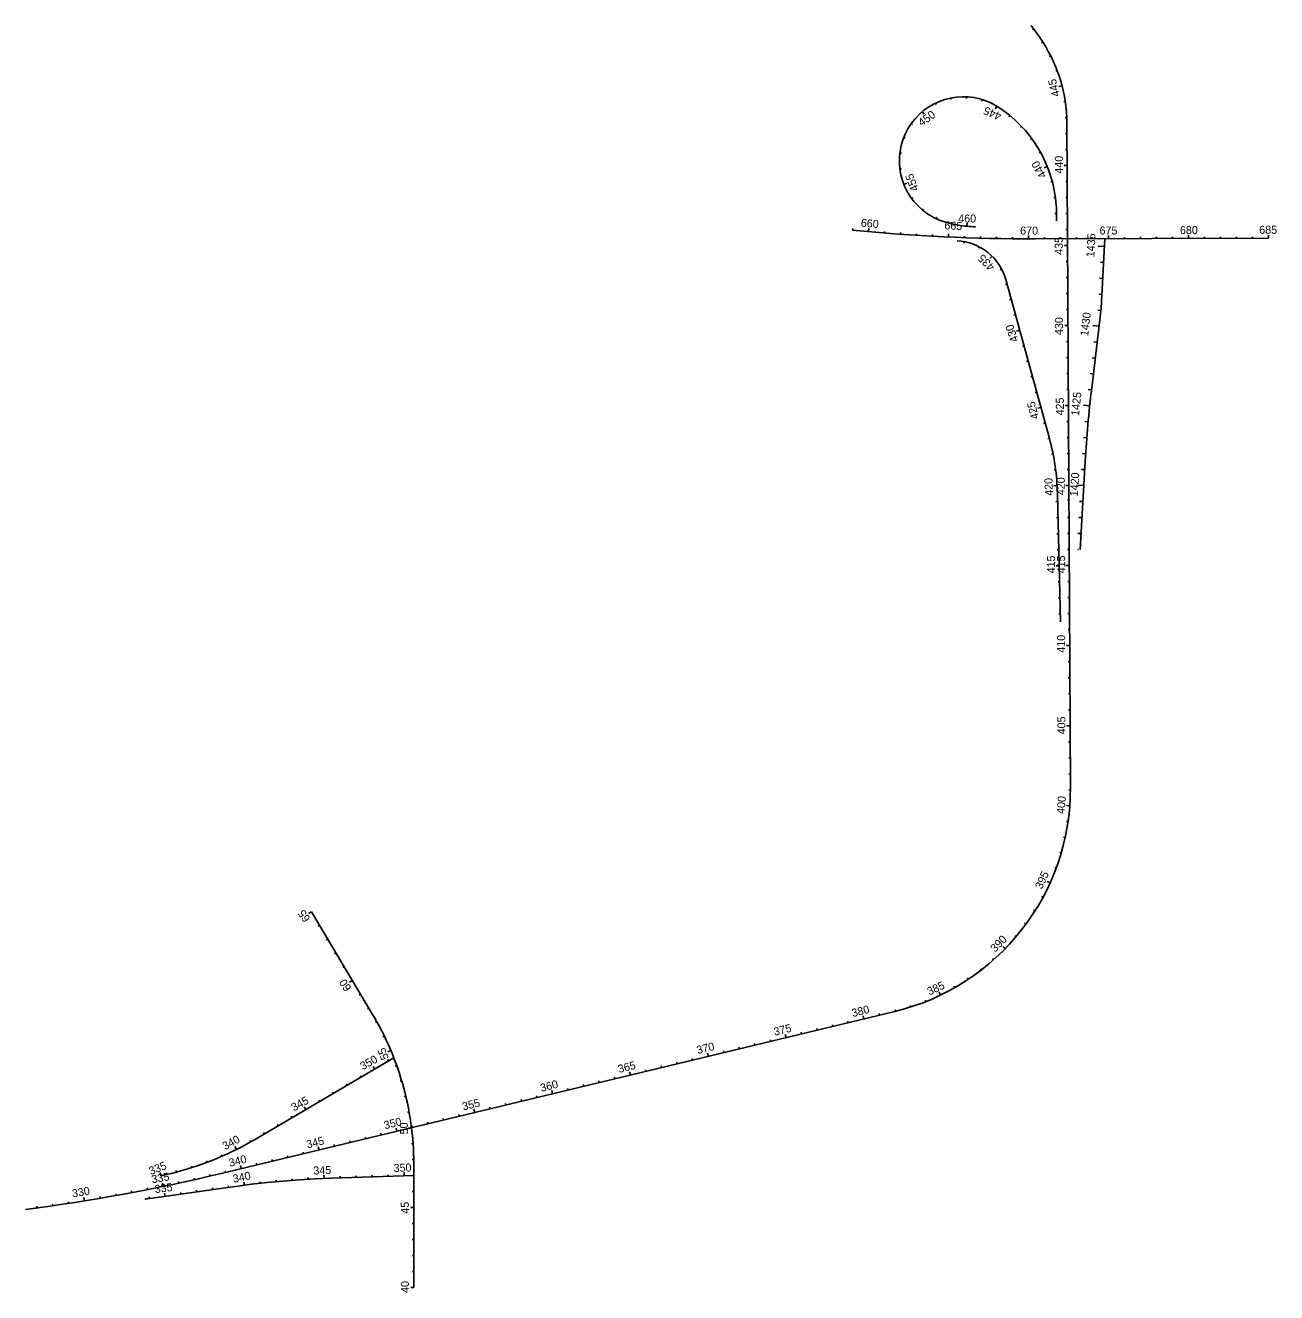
# Model space of a CAD drawing. Extents: x 448091 to 665917, y 1461380 to 1587607.
# Drawn here: x 588301 to 596117, y 1531698 to 1539615 of the extents above; entities that cross this region are included whole.
import ezdxf

# ---------------------------------------------------------------- set-up
doc = ezdxf.new("R2010")
doc.units = 0
doc.layers.add('TextShtNo', color=7, linetype='Continuous')
doc.layers.add('TextTitle', color=7, linetype='Continuous')

msp = doc.modelspace()

# ---------------------------------------------------------------- linework, layer by layer
at = {"layer": 'TextShtNo'}
for p, q in [((594807.2, 1539001), (594810.8, 1538304.1)), ((594742.4, 1538392.9), (594742.1, 1538437.7)), ((594608.9, 1538280.9), (596066.2, 1538284.4)), ((594810.8, 1538304.1), (594828.8, 1534854.9)), ((595020.8, 1537847.2), (595044.1, 1538282.5)), ((594697.4, 1537034.2), (594424.4, 1538026.1)), ((594961.4, 1537347.6), (595020.8, 1537847.2)), ((594888.8, 1536340.3), (594921, 1536890.8)), ((594767.4, 1535889.4), (594747.3, 1536687.2)), ((590469.4, 1533436.6), (590087.5, 1534077.8)), ((590481, 1533416.9), (590469.4, 1533436.6)), ((590496.8, 1533389.1), (590481, 1533416.9)), ((590512.2, 1533361.1), (590496.8, 1533389.1)), ((590526.9, 1533332.7), (590512.2, 1533361.1)), ((590541.2, 1533304.1), (590526.9, 1533332.7)), ((590555, 1533275.2), (590541.2, 1533304.1)), ((590568.4, 1533246.1), (590555, 1533275.2)), ((590581, 1533216.8), (590568.4, 1533246.1)), ((590593.3, 1533187.3), (590581, 1533216.8)), ((589727.7, 1532651.4), (590602.6, 1533164)), ((590605.1, 1533157.6), (590593.3, 1533187.3)), ((590616.3, 1533127.6), (590605.1, 1533157.6)), ((590627, 1533097.6), (590616.3, 1533127.6)), ((590637.3, 1533067.2), (590627, 1533097.6)), ((590646.8, 1533036.8), (590637.3, 1533067.2)), ((590656, 1533006), (590646.8, 1533036.8)), ((590664.5, 1532975.2), (590656, 1533006)), ((590672.6, 1532944.3), (590664.5, 1532975.2)), ((590680.1, 1532913.3), (590672.6, 1532944.3)), ((590687.1, 1532882), (590680.1, 1532913.3)), ((590693.4, 1532850.7), (590687.1, 1532882)), ((590699.3, 1532819.4), (590693.4, 1532850.7)), ((590704.6, 1532787.7), (590699.3, 1532819.4)), ((590709.4, 1532756.2), (590704.6, 1532787.7)), ((590713.7, 1532724.5), (590709.4, 1532756.2)), ((590717.2, 1532692.6), (590713.7, 1532724.5)), ((589707.3, 1532639.5), (589727.7, 1532651.4)), ((590720.3, 1532660.9), (590717.2, 1532692.6)), ((590722.9, 1532629), (590720.3, 1532660.9)), ((589559.1, 1532563.5), (589589.2, 1532577.7)), ((589589.2, 1532577.7), (589619.1, 1532592.5)), ((589619.1, 1532592.5), (589648.7, 1532607.5)), ((589648.7, 1532607.5), (589678.2, 1532623.4)), ((589678.2, 1532623.4), (589707.3, 1532639.5)), ((590724.8, 1532597), (590722.9, 1532629)), ((590726.3, 1532565.1), (590724.8, 1532597)), ((590727.3, 1532533.2), (590726.3, 1532565.1)), ((589341.5, 1532479.4), (589373.3, 1532489.7)), ((589373.3, 1532489.7), (589404.8, 1532500.7)), ((589404.8, 1532500.7), (589435.9, 1532512.2)), ((589435.9, 1532512.2), (589467.2, 1532524.3)), ((589467.2, 1532524.3), (589497.9, 1532536.9)), ((589497.9, 1532536.9), (589528.6, 1532549.8)), ((589528.6, 1532549.8), (589559.1, 1532563.5)), ((590727.5, 1532501.2), (590727.3, 1532533.2)), ((590728.3, 1531729.5), (590727.5, 1532501.2)), ((589148.1, 1532428.8), (589180.8, 1532435.8)), ((589180.8, 1532435.8), (589213.2, 1532443.4)), ((589213.2, 1532443.4), (589245.4, 1532451.6)), ((589245.4, 1532451.6), (589277.8, 1532460.3)), ((589277.8, 1532460.3), (589309.8, 1532469.6)), ((589309.8, 1532469.6), (589341.5, 1532479.4)), ((590011.7, 1532403), (590111.2, 1532409.1)), ((590111.2, 1532409.1), (590211.4, 1532412.9)), ((590211.4, 1532412.9), (590727.6, 1532429.5)), ((590211.4, 1532412.9), (590211.4, 1532412.9)), ((589050, 1532282.7), (589595.4, 1532359.6)), ((589595.4, 1532359.6), (589614, 1532362.1)), ((589595.4, 1532359.6), (589595.4, 1532359.6)), ((589614, 1532362.1), (589712.7, 1532375)), ((589712.7, 1532375), (589812.1, 1532386.2)), ((589812.1, 1532386.2), (589912.2, 1532395.2)), ((589912.2, 1532395.2), (590011.7, 1532403))]:
    msp.add_line(p, q, dxfattribs=at)
for points in [[(594632.8, 1539544.7), (594583.4, 1539614.6)], [(593905.5, 1538460.3), (593908.3, 1538458), (593913.7, 1538453.7), (593919.3, 1538449.4), (593924.9, 1538445.3), (593930.6, 1538441.2), (593936.3, 1538437.2), (593942.2, 1538433.4), (593948, 1538429.6), (593954, 1538426), (593960, 1538422.4), (593966.1, 1538419), (593972.2, 1538415.6), (593978.4, 1538412.4), (593984.6, 1538409.3), (593991, 1538406.3), (593997.3, 1538403.4), (594003.7, 1538400.6), (594010.2, 1538397.9), (594016.6, 1538395.4), (594023.2, 1538392.9), (594029.8, 1538390.6), (594036.4, 1538388.4), (594043, 1538386.3), (594049.7, 1538384.3), (594056.4, 1538382.4), (594058.1, 1538382), (594058.1, 1538382), (594071.6, 1538378.5), (594085.2, 1538375.3), (594098.8, 1538372.4), (594112.6, 1538369.6), (594126.3, 1538367.1), (594140, 1538364.9), (594153.9, 1538362.8), (594167.7, 1538361), (594181.6, 1538359.5), (594182.4, 1538359.5)], [(594742.1, 1538437.7), (594742, 1538451.5), (594741.5, 1538465.5), (594740.8, 1538479.4), (594740.2, 1538488.9)], [(594182.4, 1538359.5), (594195.5, 1538358.3), (594209.4, 1538357.2), (594223.3, 1538356.4), (594235.8, 1538355.9)], [(589524.8, 1532443.3), (593731.3, 1533454.8)]]:
    msp.add_lwpolyline(points, dxfattribs=at)
for centre, radius, start, end in [((593857.2, 1538996.1), 950, 0.29776, 35.26971), ((594160.2, 1538768.7), 400, 58.54689, 230.43574), ((593942.1, 1538433.3), 800, 3.98524, 57.75864), ((594581.1, 1549718), 11437.2, 264.41492, 270.13917), ((594106.2, 1537938.5), 330, 15.38847, 87.53834), ((602547.4, 1536445.8), 7639.4, 173.22068, 176.66075), ((593315.2, 1536658.3), 1432.4, 1.15557, 15.21148), ((593396.4, 1534847.5), 1432.4, 283.52028, 0.29778), ((586845.8, 1543584.9), 11459.2, 277.29529, 283.52026)]:
    msp.add_arc(centre, radius, start, end, dxfattribs=at)
at = {"layer": 'TextTitle'}
for p, q in [((594590.8, 1539586.7), (594599, 1539592.5)), ((594647.6, 1539504.9), (594656, 1539510.4)), ((594696.7, 1539419.1), (594705.6, 1539423.6)), ((594736.5, 1539328.5), (594745.8, 1539332.1)), ((594756.9, 1539231.8), (594776.2, 1539236.8)), ((594082.3, 1539150.9), (594080.3, 1539160.7)), ((594179.3, 1539158.3), (594179.8, 1539168.2)), ((594275.1, 1539141.4), (594278, 1539151)), ((594786.5, 1539137.5), (594796.4, 1539139)), ((593915.1, 1539059.1), (593902.2, 1539074.4)), ((593990.2, 1539119.7), (593985.9, 1539128.7)), ((594358.3, 1539093), (594368.9, 1539109.9)), ((593842.7, 1538995.2), (593834.6, 1539001)), ((594443.6, 1539043.7), (594450, 1539051.5)), ((594515.8, 1538976.4), (594523.1, 1538983.3)), ((594796.2, 1539039), (594806.2, 1539039.5)), ((593796.6, 1538909.7), (593787.3, 1538913.3)), ((594579.1, 1538900.7), (594587.1, 1538906.6)), ((594807.5, 1538939.6), (594797.5, 1538939.5)), ((594632.4, 1538817.6), (594641.1, 1538822.5)), ((594808.1, 1538839.6), (594798, 1538839.5)), ((593773, 1538815.3), (593763.1, 1538816.5)), ((594808.6, 1538739.6), (594788.6, 1538739.5)), ((593773.5, 1538718.1), (593763.6, 1538716.8)), ((594665.6, 1538724.8), (594684.2, 1538732.3)), ((593807.4, 1538627.7), (593788.8, 1538620.3)), ((594706, 1538634.9), (594715.7, 1538637.5)), ((594809.1, 1538639.6), (594799.1, 1538639.5)), ((593845.1, 1538538.9), (593837.1, 1538533)), ((594725.2, 1538538.1), (594735.1, 1538539.4)), ((594809.6, 1538539.6), (594799.6, 1538539.5)), ((593911.7, 1538467.9), (593905.4, 1538460.4)), ((593905.5, 1538460.3), (593905.4, 1538460.4)), ((594732.1, 1538439.6), (594742.1, 1538439.8)), ((594810.1, 1538439.6), (594800.1, 1538439.5)), ((593468, 1538335.1), (593469, 1538345.1)), ((593567.6, 1538325.8), (593569.4, 1538345.7)), ((593993.8, 1538415.5), (593989.6, 1538406.9)), ((594086.6, 1538385.1), (594084.4, 1538375.5)), ((594184.2, 1538379.4), (594182.4, 1538359.5)), ((593667.2, 1538317.4), (593668, 1538327.4)), ((593766.9, 1538309.8), (593767.7, 1538319.8)), ((593866.7, 1538303.2), (593867.3, 1538313.1)), ((593966.5, 1538297.3), (593967.1, 1538307.3)), ((594066.4, 1538292.4), (594067.3, 1538312.4)), ((594166.3, 1538288.3), (594166.7, 1538298.3)), ((594266.3, 1538285.2), (594266.6, 1538295.2)), ((594366.3, 1538282.8), (594366.4, 1538292.8)), ((594466.3, 1538281.4), (594466.4, 1538291.4)), ((594566.2, 1538280.8), (594566.3, 1538300.8)), ((594666.3, 1538281), (594666.2, 1538291)), ((594766.3, 1538281.2), (594766.2, 1538291.2)), ((594810.7, 1538339.6), (594800.6, 1538339.5)), ((594866.3, 1538281.5), (594866.2, 1538291.5)), ((594926.7, 1538288.1), (594923.8, 1538278.5)), ((594966.3, 1538281.7), (594966.2, 1538291.7)), ((595066.2, 1538282), (595066.2, 1538302)), ((595166.2, 1538282.2), (595166.2, 1538292.2)), ((595266.2, 1538282.5), (595266.2, 1538292.5)), ((595366.2, 1538282.7), (595366.2, 1538292.7)), ((595466.2, 1538282.9), (595466.2, 1538292.9)), ((595566.2, 1538283.2), (595566.2, 1538303.2)), ((595666.2, 1538283.4), (595666.2, 1538293.4)), ((595766.2, 1538283.7), (595766.2, 1538293.7)), ((595866.2, 1538283.9), (595866.2, 1538293.9)), ((595966.2, 1538284.2), (595966.2, 1538294.2)), ((596066.2, 1538284.4), (596066.2, 1538304.4)), ((594162.2, 1538253.6), (594164, 1538263.4)), ((594253.7, 1538222.5), (594258.3, 1538231.4)), ((594811.2, 1538239.6), (594791.2, 1538239.5)), ((595041.5, 1538233.1), (595001.5, 1538235.2)), ((594324.7, 1538158.5), (594338.8, 1538172.7)), ((594811.7, 1538139.6), (594801.7, 1538139.5)), ((595036.1, 1538133.2), (595016.1, 1538134.3)), ((594389.2, 1538088), (594398, 1538092.6)), ((594812.2, 1538039.7), (594802.2, 1538039.6)), ((595030.8, 1538033.4), (595010.8, 1538034.5)), ((594422.3, 1537996.2), (594431.9, 1537998.8)), ((594448.8, 1537899.8), (594458.5, 1537902.4)), ((594812.7, 1537939.7), (594802.7, 1537939.6)), ((595025.4, 1537933.5), (595005.4, 1537934.6)), ((594475.3, 1537803.4), (594485, 1537806)), ((594813.2, 1537839.7), (594803.2, 1537839.6)), ((595019.2, 1537833.8), (594999.3, 1537836.1)), ((594492.2, 1537704.3), (594511.5, 1537709.6)), ((594813.8, 1537739.7), (594793.8, 1537739.6)), ((594813.8, 1537739.7), (594803.5, 1537739.6)), ((595007.4, 1537734.5), (594967.7, 1537739.2)), ((594814.3, 1537639.7), (594804.3, 1537639.6)), ((594995.6, 1537635.2), (594975.7, 1537637.5)), ((594528.4, 1537610.5), (594538.1, 1537613.2)), ((594555, 1537514.1), (594564.6, 1537516.8)), ((594814.8, 1537539.7), (594804.8, 1537539.6)), ((594983.8, 1537535.9), (594963.9, 1537538.2)), ((594581.5, 1537417.7), (594591.1, 1537420.3)), ((594815.3, 1537439.7), (594805.3, 1537439.6)), ((594972, 1537436.6), (594952.1, 1537438.9)), ((594608, 1537321.3), (594617.7, 1537323.9)), ((594815.8, 1537339.7), (594805.8, 1537339.6)), ((594960.2, 1537337.2), (594940.3, 1537339.6)), ((594816.4, 1537239.7), (594796.4, 1537239.6)), ((594949.2, 1537237.9), (594909.4, 1537242)), ((594624.9, 1537222.2), (594644.2, 1537227.5)), ((594661.1, 1537128.4), (594670.7, 1537131.1)), ((594816.9, 1537139.7), (594806.9, 1537139.6)), ((594939.4, 1537138.3), (594919.5, 1537140.1)), ((594687.8, 1537031.5), (594697.4, 1537034.2)), ((594817.4, 1537039.7), (594807.4, 1537039.6)), ((594931, 1537038.7), (594911.1, 1537040.2)), ((594710.4, 1536935.4), (594720.2, 1536937.4)), ((594817.9, 1536939.7), (594807.9, 1536939.6)), ((594923.9, 1536938.9), (594904, 1536940.2)), ((594726.3, 1536837.4), (594736.2, 1536838.7)), ((594818.4, 1536839.7), (594808.4, 1536839.6)), ((594917.9, 1536839.1), (594898, 1536840.3)), ((594725.4, 1536738), (594745.3, 1536739.1)), ((594819, 1536739.7), (594799, 1536739.6)), ((594912.1, 1536739.3), (594872.2, 1536741.6)), ((594738.5, 1536638.9), (594748.5, 1536639.2)), ((594819.4, 1536651.7), (594809.4, 1536651.6)), ((594906.3, 1536639.5), (594886.3, 1536640.6)), ((594741, 1536539), (594751, 1536539.2)), ((594820, 1536539.7), (594810, 1536539.6)), ((594900.5, 1536539.6), (594880.5, 1536540.8)), ((594743.6, 1536439), (594753.6, 1536439.2)), ((594820.5, 1536439.7), (594810.5, 1536439.6)), ((594894.6, 1536439.8), (594874.7, 1536441)), ((594746.1, 1536339), (594756.1, 1536339.3)), ((594821, 1536339.7), (594811, 1536339.6)), ((594879.1, 1536339.9), (594874.9, 1536340.2)), ((594738.6, 1536238.8), (594758.6, 1536239.3)), ((594821.6, 1536239.7), (594801.6, 1536239.6)), ((594751.1, 1536139.1), (594761.1, 1536139.3)), ((594822.1, 1536139.7), (594812.1, 1536139.6)), ((594753.6, 1536039.1), (594763.6, 1536039.4)), ((594822.6, 1536039.7), (594812.6, 1536039.6)), ((594756.1, 1535939.1), (594766.1, 1535939.4)), ((594823.1, 1535939.7), (594813.1, 1535939.6)), ((594823.6, 1535839.7), (594813.6, 1535839.6)), ((594824.2, 1535739.7), (594804.2, 1535739.6)), ((594824.7, 1535639.7), (594814.7, 1535639.6)), ((594825.2, 1535539.7), (594815.2, 1535539.6)), ((594825.7, 1535439.7), (594815.7, 1535439.6)), ((594826.2, 1535339.7), (594816.2, 1535339.7)), ((594826.8, 1535239.7), (594806.8, 1535239.6)), ((594827.3, 1535139.7), (594817.3, 1535139.7)), ((594827.8, 1535039.7), (594817.8, 1535039.7)), ((594828.3, 1534939.7), (594818.3, 1534939.7)), ((594828.8, 1534839.7), (594818.8, 1534839.8)), ((594824.7, 1534739.8), (594804.8, 1534741.3)), ((594813.7, 1534640.4), (594803.8, 1534641.9)), ((594795.8, 1534542.1), (594786.1, 1534544.2)), ((594771.1, 1534445.2), (594761.5, 1534448)), ((594739.7, 1534350.3), (594730.3, 1534353.7)), ((594701.8, 1534257.8), (594683.5, 1534266)), ((594657.5, 1534168.2), (594648.7, 1534172.9)), ((590087.5, 1534077.8), (590070.4, 1534067.5)), ((594607, 1534081.8), (594598.5, 1534087.2)), ((590138.7, 1533991.9), (590130.1, 1533986.7)), ((594550.6, 1533999.3), (594542.6, 1534005.2)), ((594488.7, 1533920.8), (594481, 1533927.3)), ((590189.9, 1533905.9), (590181.3, 1533900.8)), ((594421.4, 1533846.9), (594407.1, 1533860.8)), ((590241.1, 1533820), (590232.5, 1533814.9)), ((594349.1, 1533777.8), (594342.4, 1533785.3)), ((590292.2, 1533734.1), (590283.6, 1533729)), ((594272.1, 1533714), (594266, 1533721.9)), ((590343.4, 1533648.2), (590326.2, 1533638)), ((594105.9, 1533603.1), (594100.9, 1533611.8)), ((594190.9, 1533655.6), (594185.4, 1533664)), ((590394.6, 1533562.3), (590386, 1533557.2)), ((593925.8, 1533516.5), (593922.1, 1533525.8)), ((594017.3, 1533556.6), (594008.7, 1533574.7)), ((590445.8, 1533476.4), (590437.2, 1533471.2)), ((593635.7, 1533431.8), (593633.4, 1533441.5)), ((593735.4, 1533455.8), (593733, 1533465.5)), ((593831.6, 1533482.8), (593828.6, 1533492.3)), ((590496.2, 1533390), (590487.5, 1533385.1)), ((593344.1, 1533361.6), (593341.7, 1533371.4)), ((593441.3, 1533385), (593438.9, 1533394.7)), ((593538.5, 1533408.4), (593533.8, 1533427.8)), ((593538.5, 1533408.4), (593536.2, 1533418.1)), ((590542.5, 1533301.4), (590533.4, 1533297.1)), ((592955.1, 1533268.1), (592952.8, 1533277.9)), ((593052.4, 1533291.5), (593047.7, 1533311)), ((593149.6, 1533314.9), (593147.3, 1533324.6)), ((593246.8, 1533338.2), (593244.5, 1533348)), ((590583.7, 1533210.3), (590565.4, 1533202.6)), ((592663.5, 1533198), (592661.1, 1533207.7)), ((592760.7, 1533221.3), (592758.3, 1533231.1)), ((592857.9, 1533244.7), (592855.6, 1533254.5)), ((590570.1, 1533145), (590565.1, 1533153.6)), ((592371.8, 1533127.9), (592369.4, 1533137.6)), ((592469, 1533151.2), (592466.7, 1533161)), ((592566.2, 1533174.6), (592561.5, 1533194.1)), ((590397.6, 1533043.9), (590392.5, 1533052.5)), ((590483.9, 1533094.5), (590473.8, 1533111.7)), ((590620, 1533117.2), (590610.6, 1533113.8)), ((591982.9, 1533034.3), (591980.5, 1533044.1)), ((592080.1, 1533057.7), (592075.4, 1533077.2)), ((592177.3, 1533081.1), (592175, 1533090.8)), ((592274.5, 1533104.5), (592272.2, 1533114.2)), ((590311.3, 1532993.3), (590306.3, 1533002)), ((590651.2, 1533022.1), (590641.6, 1533019.3)), ((591593.9, 1532940.8), (591589.3, 1532960.3)), ((591691.2, 1532964.2), (591688.8, 1532973.9)), ((591788.4, 1532987.6), (591786, 1532997.3)), ((591885.6, 1533011), (591883.3, 1533020.7)), ((590138.7, 1532892.2), (590133.7, 1532900.9)), ((590225, 1532942.8), (590220, 1532951.4)), ((590677.1, 1532925.6), (590667.4, 1532923.2)), ((591302.2, 1532870.7), (591299.9, 1532880.4)), ((591399.5, 1532894.1), (591397.1, 1532903.8)), ((591496.7, 1532917.4), (591494.4, 1532927.2)), ((590052.5, 1532841.7), (590042.4, 1532858.9)), ((590697.7, 1532827.7), (590688, 1532825.9)), ((591010.6, 1532800.5), (591008.2, 1532810.3)), ((591107.8, 1532823.9), (591103.1, 1532843.4)), ((591205, 1532847.3), (591202.7, 1532857)), ((589879.9, 1532740.6), (589874.8, 1532749.2)), ((589966.2, 1532791.1), (589961.1, 1532799.8)), ((590621.6, 1532707), (590617, 1532726.5)), ((590713.1, 1532728.9), (590693.4, 1532726.3)), ((590713.1, 1532728.9), (590705.1, 1532727.9)), ((590718.9, 1532730.4), (590716.5, 1532740.1)), ((590816.1, 1532753.8), (590813.8, 1532763.5)), ((590913.3, 1532777.2), (590911, 1532786.9)), ((589707.3, 1532639.5), (589702.3, 1532648.2)), ((589793.6, 1532690), (589788.6, 1532698.7)), ((590330, 1532636.9), (590327.6, 1532646.6)), ((590427.2, 1532660.3), (590424.8, 1532670)), ((590524.4, 1532683.6), (590522.1, 1532693.4)), ((589619.1, 1532592.5), (589610, 1532610.3)), ((590038.3, 1532566.7), (590035.9, 1532576.5)), ((590135.5, 1532590.1), (590130.8, 1532609.6)), ((590232.7, 1532613.5), (590230.4, 1532623.2)), ((590722.9, 1532629.4), (590712.9, 1532628.6)), ((589341.5, 1532479.5), (589338.5, 1532489)), ((589436, 1532512.2), (589432.4, 1532521.5)), ((589528.7, 1532549.8), (589524.5, 1532559)), ((589649.4, 1532473.2), (589644.7, 1532492.7)), ((589746.6, 1532496.6), (589744.2, 1532506.3)), ((589843.8, 1532520), (589841.5, 1532529.7)), ((589941, 1532543.4), (589938.7, 1532553.1)), ((590727.3, 1532529.5), (590717.3, 1532529.5)), ((589148.1, 1532428.8), (589144, 1532448.4)), ((589245.5, 1532451.6), (589242.9, 1532461.3)), ((589357.3, 1532404.8), (589355.1, 1532414.1)), ((589454.7, 1532427.1), (589452.6, 1532436.5)), ((589552.1, 1532449.8), (589549.8, 1532459.6)), ((589967.4, 1532399.5), (589966.7, 1532409.5)), ((590067.2, 1532406.4), (590066.6, 1532416.4)), ((590167.1, 1532411.2), (590166.3, 1532431.2)), ((590267, 1532414.7), (590266.7, 1532424.7)), ((590367, 1532417.9), (590366.6, 1532427.9)), ((590466.9, 1532421.1), (590466.6, 1532431.1)), ((590566.9, 1532424.3), (590566.5, 1532434.3)), ((590666.8, 1532427.6), (590666.2, 1532447.6)), ((590727.6, 1532429.5), (590717.6, 1532429.5)), ((588965.6, 1532324), (588963.8, 1532333.4)), ((589063.9, 1532342.3), (589062, 1532352.3)), ((589161.8, 1532362.3), (589157.7, 1532381.8)), ((589259.7, 1532382.9), (589257.6, 1532392.7)), ((589371.9, 1532328.1), (589370.5, 1532338)), ((589470.9, 1532342.1), (589469.5, 1532352)), ((589569.9, 1532356), (589568.5, 1532365.9)), ((589669, 1532369.3), (589666.4, 1532389.1)), ((589768.3, 1532381.3), (589767.2, 1532391.2)), ((589867.8, 1532391.2), (589866.9, 1532401.2)), ((590727.7, 1532329.5), (590717.7, 1532329.5)), ((588472.5, 1532241.5), (588471.1, 1532251.7)), ((588571.3, 1532256.3), (588569.8, 1532266.3)), ((588670.1, 1532271.9), (588667, 1532291.6)), ((588768.7, 1532288.7), (588767.1, 1532298.1)), ((588867.2, 1532305.9), (588865.6, 1532315.3)), ((589074.8, 1532286.1), (589073.4, 1532296.1)), ((589173.8, 1532300.1), (589171, 1532319.9)), ((589272.8, 1532314.1), (589271.4, 1532324)), ((588373.3, 1532228.2), (588372, 1532237.9)), ((590727.8, 1532229.5), (590707.8, 1532229.5)), ((590727.9, 1532129.5), (590717.9, 1532129.5)), ((590728, 1532029.5), (590718, 1532029.5)), ((590728.1, 1531929.5), (590718.1, 1531929.5)), ((590728.2, 1531829.5), (590718.2, 1531829.5)), ((590728.3, 1531729.5), (590708.3, 1531729.5))]:
    msp.add_line(p, q, dxfattribs=at)
for centre in [(590602.6, 1533164), (590727.6, 1532429.5), (589050, 1532282.7)]:
    msp.add_circle(centre, 0.6, dxfattribs=at)

# ---------------------------------------------------------------- texts
for s, rotation, p in [('445', 103.45053, (594762.4, 1539175.7)), ('450', 35.20821, (593899.2, 1538981.4)), ('445', 156.32371, (594402.5, 1539064.5)), ('440', 120.24476, (594681.6, 1538677.1)), ('440', 90.29778, (594781.9, 1538688.1)), ('455', 111.08241, (593882.1, 1538589.3)), ('460', 359.90224, (594127.7, 1538383.1)), ('660', 354.91588, (593517.9, 1538357.5)), ('665', 357.42069, (594040.5, 1538340.5)), ('670', 359.92549, (594514.7, 1538307.3)), ('675', 0.13916, (595010.6, 1538307.7)), ('680', 0.13916, (595512.8, 1538310.6)), ('685', 0.13916, (596008, 1538312.2)), ('435', 90.29778, (594781.1, 1538181.3)), ('1435', 86.93389, (594977.7, 1538165)), ('435', 134.61516, (594359.7, 1538110.1)), ('430', 90.29778, (594782, 1537679.9)), ('1430', 83.22068, (594939.4, 1537671.2)), ('430', 109.12057, (594504.9, 1537645.7)), ('1425', 84.04899, (594882.1, 1537173.4)), ('425', 104.70994, (594632.6, 1537161.1)), ('425', 90.29778, (594787.8, 1537178.1)), ('420', 92.87972, (594720.7, 1536677)), ('420', 90.29778, (594793.8, 1536679.7)), ('1420', 86.29778, (594874.5, 1536671.1)), ('415', 90.29778, (594732.6, 1536191.1)), ('415', 90.29778, (594796.1, 1536191.1)), ('410', 90.29778, (594795.8, 1535695.7)), ('405', 90.29778, (594797.6, 1535185.7)), ('400', 85.69028, (594791.8, 1534687)), ('395', 65.69028, (594650.5, 1534214.5)), ('65', 124.99989, (590083.4, 1534034.5)), ('390', 45.69027, (594358.5, 1533821.5)), ('60', 124.99988, (590340.8, 1533602.2)), ('385', 24.81529, (593947.5, 1533553.6)), ('380', 13.99995, (593469.1, 1533419.3)), ('375', 13.99995, (592981.9, 1533302)), ('55', 112.05979, (590573.2, 1533163.8)), ('370', 13.99995, (592500.7, 1533187.9)), ('350', 29.00004, (590408.8, 1533087.1)), ('365', 13.99995, (592009.5, 1533069.9)), ('360', 13.99995, (591524.2, 1532951.8)), ('345', 29.00004, (589978.7, 1532829.7)), ('355', 13.99995, (591036.6, 1532835.6)), ('350', 13.99992, (590547.1, 1532718)), ('50', 92.00001, (590691.9, 1532687.6)), ('340', 29.00004, (589549, 1532587)), ('345', 13.99992, (590062.9, 1532598.4)), ('335', 21.18475, (589084, 1532432)), ('340', 13.99992, (589578.8, 1532484)), ('345', 1.99999, (590100.8, 1532435.8)), ('350', 2.00001, (590601.9, 1532451.6)), ('335', 9.99996, (589093.7, 1532380.8)), ('340', 12.05269, (589602.9, 1532384)), ('330', 9.99996, (588597, 1532292.2)), ('335', 7.28905, (589112.1, 1532319.5)), ('45', 92.00001, (590697.8, 1532192.2)), ('40', 91.99999, (590698.8, 1531697.1))]:
    msp.add_text(s, height=50, rotation=rotation, dxfattribs=at).set_placement(p)

doc.saveas('drawing.dxf')
